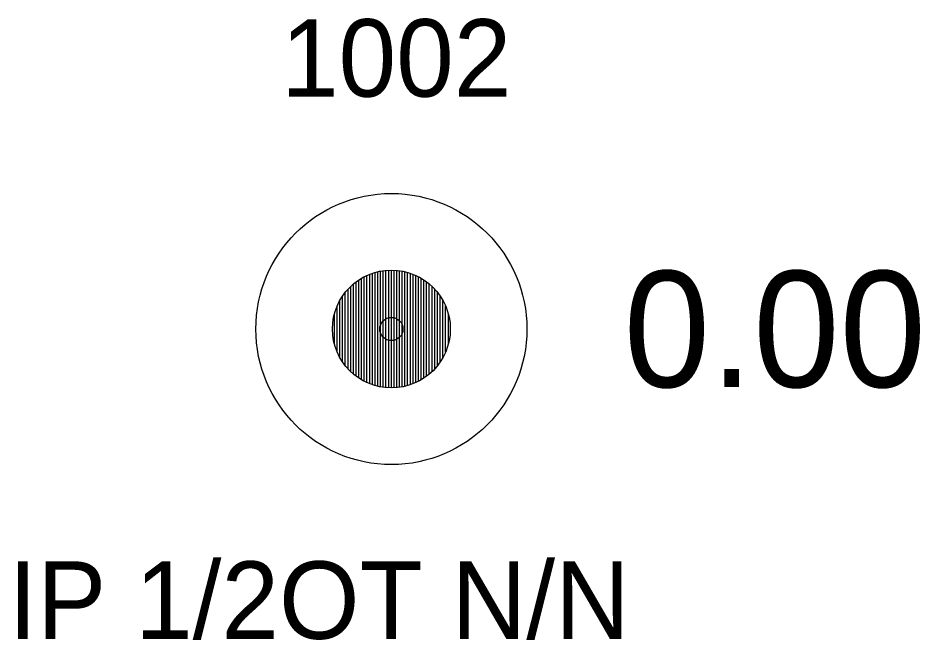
# Model space of a CAD drawing. Extents: x 1393163 to 1398407, y 1072670 to 1074651.
# Drawn here: x 1394258.82 to 1394270.47, y 1073573.94 to 1073581.97 of the extents above; entities that cross this region are included whole.
import ezdxf

# ---------------------------------------------------------------- set-up
doc = ezdxf.new("R2010")
doc.units = 0
for name, color, linetype in [('RD_EX_DV_Prop_txCode', 7, 'Continuous'), ('RD_EX_DV_PropPin', 7, 'Continuous'), ('RD_EX_TX_DV_Prop_ELEV', 7, 'Continuous'), ('RD_SMD_Locator', 7, 'Continuous')]:
    doc.layers.add(name, color=color, linetype=linetype)

msp = doc.modelspace()

# ---------------------------------------------------------------- linework, layer by layer
at = {"layer": 'RD_EX_DV_PropPin'}
for p, q in [((1394263.329, 1073577.258), (1394263.329, 1073578.644)), ((1394263.364, 1073577.243), (1394263.364, 1073578.658)), ((1394263.399, 1073577.23), (1394263.399, 1073578.671)), ((1394263.434, 1073577.219), (1394263.434, 1073578.682)), ((1394263.469, 1073577.21), (1394263.469, 1073578.692)), ((1394263.504, 1073577.203), (1394263.504, 1073578.699)), ((1394263.539, 1073577.197), (1394263.539, 1073578.705)), ((1394263.574, 1073577.193), (1394263.574, 1073578.709)), ((1394263.609, 1073577.191), (1394263.609, 1073578.711)), ((1394263.644, 1073577.19), (1394263.644, 1073578.712)), ((1394263.679, 1073577.191), (1394263.679, 1073578.711)), ((1394263.714, 1073577.193), (1394263.714, 1073578.709)), ((1394263.749, 1073577.197), (1394263.749, 1073578.705)), ((1394263.784, 1073577.203), (1394263.784, 1073578.699)), ((1394263.819, 1073577.21), (1394263.819, 1073578.692)), ((1394263.854, 1073577.219), (1394263.854, 1073578.682)), ((1394263.889, 1073577.23), (1394263.889, 1073578.671)), ((1394263.924, 1073577.243), (1394263.924, 1073578.658)), ((1394263.959, 1073577.258), (1394263.959, 1073578.644)), ((1394263.154, 1073577.369), (1394263.154, 1073578.533)), ((1394263.189, 1073577.341), (1394263.189, 1073578.561)), ((1394263.224, 1073577.316), (1394263.224, 1073578.585)), ((1394263.259, 1073577.295), (1394263.259, 1073578.607)), ((1394263.294, 1073577.275), (1394263.294, 1073578.627)), ((1394263.994, 1073577.275), (1394263.994, 1073578.627)), ((1394264.029, 1073577.295), (1394264.029, 1073578.607)), ((1394264.064, 1073577.316), (1394264.064, 1073578.585)), ((1394264.099, 1073577.341), (1394264.099, 1073578.561)), ((1394264.134, 1073577.369), (1394264.134, 1073578.533)), ((1394263.049, 1073577.477), (1394263.049, 1073578.425)), ((1394263.084, 1073577.436), (1394263.084, 1073578.466)), ((1394263.119, 1073577.4), (1394263.119, 1073578.502)), ((1394264.169, 1073577.4), (1394264.169, 1073578.502)), ((1394264.205, 1073577.436), (1394264.205, 1073578.466)), ((1394264.24, 1073577.477), (1394264.24, 1073578.425)), ((1394262.979, 1073577.581), (1394262.979, 1073578.32)), ((1394263.014, 1073577.524), (1394263.014, 1073578.377)), ((1394264.275, 1073577.524), (1394264.275, 1073578.377)), ((1394264.31, 1073577.581), (1394264.31, 1073578.32)), ((1394262.944, 1073577.653), (1394262.944, 1073578.249)), ((1394264.345, 1073577.653), (1394264.345, 1073578.249)), ((1394262.909, 1073577.755), (1394262.909, 1073578.147)), ((1394264.38, 1073577.755), (1394264.38, 1073578.147))]:
    msp.add_line(p, q, dxfattribs=at)
for radius in [1.75, 0.761]:
    msp.add_circle((1394263.644, 1073577.951), radius, dxfattribs=at)
at = {"layer": 'RD_SMD_Locator'}
msp.add_circle((1394263.644, 1073577.951), 0.15, dxfattribs=at)

# ---------------------------------------------------------------- texts
at = {"layer": 'RD_EX_DV_Prop_txCode'}
for s, p in [('1002', (1394262.219, 1073580.951)), ('IP 1/2OT N/N', (1394258.699, 1073573.951))]:
    msp.add_text(s, height=1, dxfattribs=at).set_placement(p)
at = {"layer": 'RD_EX_TX_DV_Prop_ELEV'}
msp.add_text('0.00', height=1.5, dxfattribs=at).set_placement((1394266.644, 1073577.201))

doc.saveas('drawing.dxf')
